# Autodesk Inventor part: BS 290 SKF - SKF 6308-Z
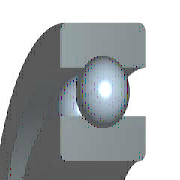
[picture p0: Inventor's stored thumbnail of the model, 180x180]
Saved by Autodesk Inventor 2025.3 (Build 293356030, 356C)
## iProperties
Created: 2024-01
Part Number: BS 290 SKF - SKF 6308-Z
Material: Acciaio, Dolce
Description: Cuscinetti a sfere con scanalatura profonda a fila singola con protezione Z SKF
Document SubType Name: Modeling
Standard: BS 290 SKF
Designer: R5800u
Standards Organization: BSI
Language: it-IT
Size Designation: SKF 6308-Z
Categories: <MemberInstance><Categories><Category DisplayName="Parti albero" InternalName="7f7aeb1f-a693-4053-b835-cee3144e0d98" Mnemonic="SHFT"><Category DisplayName="Cusc
Density: 7.85 g/cm^3
Appearance: Semilucidato
IsCustomPart: 0
Author: R5800u
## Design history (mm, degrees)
node "WorkPoint1"
node "WorkAxis1"
node "WorkPlane3"
node "WorkPlane4"
node "WorkPoint2"
pattern_circular "Seriepolare1" dims "d17" = 69 (= msp_pocet), angle "d19" = 360 deg
body "Solid1"
node "Schizzo1"
revolve "Rivoluzione1" stored, may be unused: angle "d6" = 360 deg
revolve "Rivoluzione2" stored, may be unused: angle "d10" = 360 deg
node "Schizzo4"
revolve "Rivoluzione3" stored, may be unused: angle "d16" = 360 deg
fillet "Raccordo1" dims "d20" = 1.5 (= r)
sketch "Schizzo2"
  geometry: L1 (20, 23)-(45, 23); L2 (20, 0)-(20, 23); L3 (45, 0)-(20, 0); L4 (45, 23)-(45, 0); L5 (0, 0)-(0, 20); L6 (0, 0)-(0, 20); L7 (-7.2, 0)-(43.2, 0) reference
  constraints: 12 end point, 3 vertical, 2 horizontal, 1 collinear, 1 other
  dimensions: "d1" = 40 diameter of L1.start L5 (= Diam); "d3" = 90 diameter of L1.end L5 (= DD); "d5" = 23 distance of L2.start L1.start (= msp_mdtd2)
sketch "Schizzo3"
  geometry: L1 (37, 23)-(37, 17.5); L2 (28, 23)-(37, 23); L3 (28, 17.5)-(28, 23); L4 (28, 0)-(28, 5.5); L5 (37, 0)-(28, 0); L6 (37, 5.5)-(37, 0); L7 (45, 0)-(-45, 0) reference; L8 (45, 23)-(-45, 23) reference; L9 (0, -42.29)-(0, 61.29); L10 (0, 82.007)-(0, -63.007) reference; A1 r 7.5 centre (32.5, 11.5) between (37, 5.5) and (37, 17.5); A2 r 7.5 centre (32.5, 11.5) between (28, 17.5) and (28, 5.5)
  constraints: 14 end point, 4 collinear, 4 point on circle, 4 vertical, 2 centre point, 2 concentric, 2 horizontal, 2 point on line
  dimensions: "d9" = 15 diameter of A1 (= msp_mdtd6); "d21" = 28 distance between parallel lines of L9 L4 (= 0.5 x msp_d1); "d22" = 32.5 distance from line of L9 A1.centre (= 0.5 x msp_ds); "d23" = 37 distance between parallel lines of L9 L6 (= 0.5 x msp_dd1)
sketch "Schizzo5"
  geometry: L1 (32.5, 4)-(32.5, 19); L2 (37, 0)-(-37, 0) reference; L3 (32.5, 4)-(32.5, 19); A1 r 7.5 centre (32.5, 11.5) between (32.5, 4) and (32.5, 19); A2 r 7.5 centre (32.5, 11.5) between (37, 5.5) and (37, 17.5) reference
  constraints: 4 end point, 2 point on circle, 1 centre point, 1 concentric, 1 vertical
  dimensions: "d13" = 0 horizontal distance of A1.centre L1.start; "d15" = 15.0001 diameter of A1 (computed from msp_mdtd6)
other parameters: "Diam" = 40 [user parameter; used in 3 equation terms], "DD" = 90 [user parameter; used in 3 equation terms], "B" = 23 [user parameter; used in 1 equation term], "r" = 1.5 [user parameter; used in 1 equation term], "msp_ds" = 65 (= 0.5 x Diam + 0.5 x DD) [user parameter; used in 5 equation terms], "msp_d0" = 15 (= -0.3 x Diam + 0.3 x DD) [user parameter; used in 4 equation terms], "msp_d1" = 56 (= msp_ds - 0.6 x msp_d0) [user parameter; used in 1 equation term], "msp_dd1" = 74 (= msp_ds + 0.6 x msp_d0) [user parameter; used in 1 equation term], "msp_pom" = 97.5 (= 1.5 x msp_ds) [user parameter; used in 1 equation term], "msp_mdtd2" = 23 (= B) [user parameter; used in 3 equation terms], "msp_mdtd4" = 65 (= msp_ds) [user parameter], "msp_mdtd6" = 15 (= msp_d0) [user parameter; used in 2 equation terms], "msp_mdtd7" = 11.5 (= 0.5 x msp_mdtd2) [user parameter], "msp_pocet" = 69 (computed from msp_d0, msp_pom) [user parameter; used in 1 equation term], "d2" = 72 (derived), "d4" = 19 (derived), "d7" = 0, "d8" = 15.6 (derived), "d11" = -23 (computed from msp_mdtd2), "d12" = 0 (derived), "d14" = 15.6001 (derived), "d26" = 0, "d27" = 0, "d28" = 0, "d29" = 0, "d30" = 0
